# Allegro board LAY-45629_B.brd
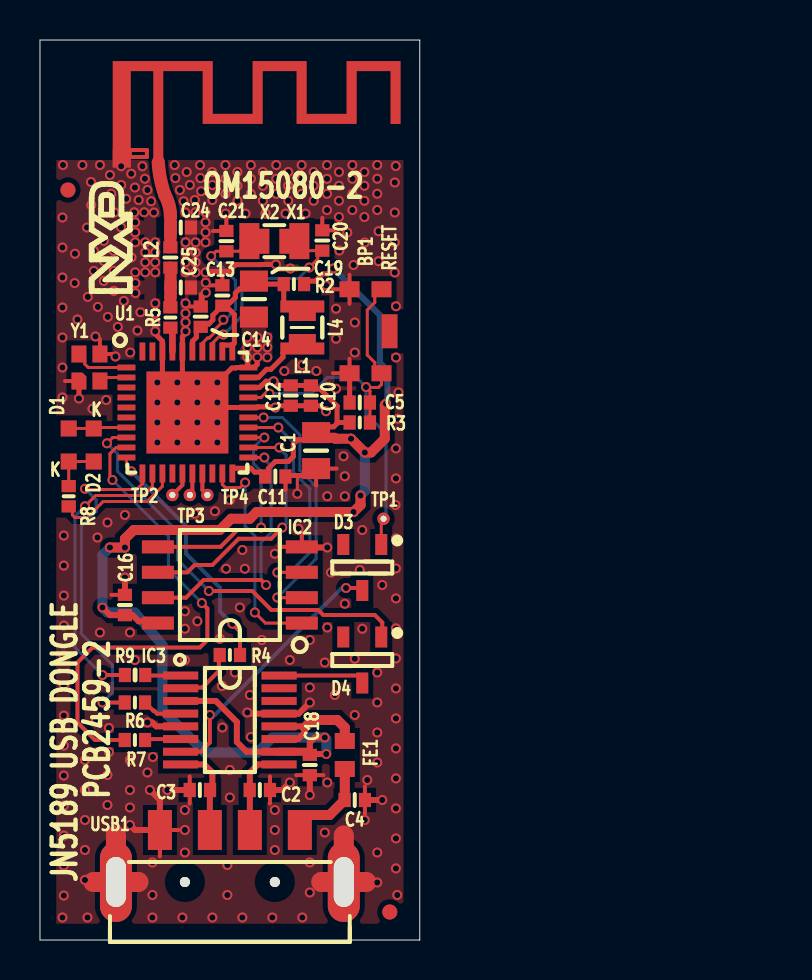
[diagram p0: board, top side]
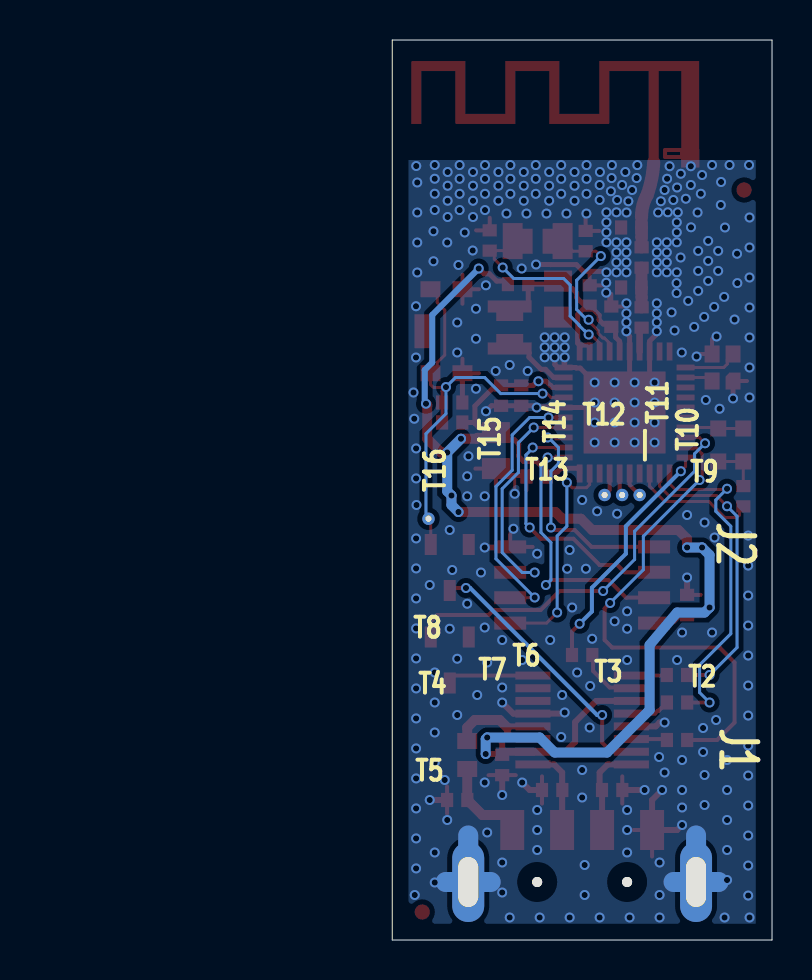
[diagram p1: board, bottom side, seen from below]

Outline 19 x 45 mm; copper layers: TOP, BOTTOM. Coordinates in mm from the lower left corner of the outline.
Outline path: 0,45 0,0 19,0 19,45 0,45

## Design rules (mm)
constraint set DEFAULT: min track width 0.15
net group ALIM: nets VCC_USB VDD
net group DEFAUT: nets N16811154 N16827974 N16827980 N16827994 N16828020 N16828026 N16828032 N16828083 N16828101 N16828111 N16845253 N16845589 N16845639 N16845653 N16845667 PIO_4/PWM4-PU PIO_5/ISP_ENTRY PIO_6/PWM6-PD PIO_7/PWM7-PD PIO_8/USART0_TXD PIO_9/USART0_RXD PIO_10/I2C0_SCL PIO_12/SWCLK PIO_13/SWDIO PIO_14/ADC0 PIO_16/SPIFI_CSN PIO_17/SPIFI_IO3 PIO_18/SPIFI_CLK PIO_19/SPIFI_IO0 PIO_20/SPIFI_IO2 PIO_21_SPIFI_IO1 RSTN
net group Z50: nets N16778908 N16845241 N16845609

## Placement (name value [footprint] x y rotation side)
1  BUBBLE-01  [BUBBLE_DIAM8]  25.05 38.5 0 top
9A_X1  BUBBLE-9A  [BUBBLE_DIAM8]  27 15.62 0 top
10A_X1  BUBBLE-10A  [BUBBLE_DIAM8]  36.62 32.88 0 top
ANT1  NC  [PCB_ANT_APPS]  5.92 38.88 0 top
BP1  KMR221GLFS  [BP_KMR]  16.29 30.44 270 top
C1  10uF  [C0805]  13.81 24.47 90 top
C2  47pF  [C0402]  11 7.5 0 top
C3  47pF  [C0402]  8 7.5 180 top
C4  10nF  [C0402]  15.75 7 0 top
C5  10nF  [C0402]  16 26.88 180 top
C10  100nF  [C0402]  13.55 27.22 90 top
C11  100nF  [C0402]  11.78 23.18 0 top
C12  47pF  [C0402]  12.54 27.22 90 top
C13  100nF  [C0402]  9.12 32.23 90 top
C14  47pF  [C0402]  8.04 31.17 90 top
C16  100nF  [C0402]  4.25 16.75 270 top
C18  100nF  [C0402]  13.5 8.75 90 top
C19  10uF  [C0805]  10.71 32.05 270 top
C20  NC  [C0402]  14.12 34.98 270 top
C21  NC  [C0402]  9.32 34.95 90 top
C24  0.8pF  [C0402]  7.04 35.62 180 top
C25  2.0pF  [C0402]  7.04 32.62 180 top
D1  ORANGE  [LED_0603_A_K]  1.44 24.75 90 top
D2  YELLOW-GREEN  [LED_0603_A_K]  2.69 24.75 270 top
D3  BAT754  [SOT23]  16.12 18.62 180 top
D4  BAT754  [SOT23]  16.12 14 180 top
FE1  470R  [BLM18]  15.25 9.25 90 top
FID1  NC  [FID1]  1.4 37.5 0 top
FID2  NC  [FID1]  17.5 1.4 0 top
IC2  MX25R8035F  [SOP8_127_200]  9.5 17.75 90 top
IC3  FT230XS  [JEDEC_MO137_AB_SSOP16]  9.5 11 270 top
L1  4,7uH_NC  [IND_CB_2518_2520]  13.12 30.62 270 top
L2  2.9nH  [SELF_0402]  6.53 34.12 270 top
L4  4.7uH  [0805C_IPCC]  13.12 30.62 270 top
NOREF  -  []  3.54 35.1 90 top
NOREF#2  -  []  0 -0.38 0 top
NOREF#3  -  []  19.38 0 90 top
NOREF#4  -  []  6 38.12 0 top
R2  NC  [R0402]  12.71 32.8 0 top
R3  2K20  [R0402]  16 25.88 180 top
R4  NC  [R0402]  9.5 14.25 180 top
R5  0R  [R0402]  6.53 31.12 270 top
R6  0R  [R0402]  4.75 11.88 0 top
R7  NC  [R0402]  4.75 10 0 top
R8  680R  [R0402]  1.44 22.19 270 top
R9  0R  [R0402]  4.76 13.25 0 top
TP1  NC  [VIA062P030]  17.19 21.06 0 top
TP2  NC  [VIA062P030]  6.62 22.25 0 top
TP3  NC  [VIA062P030]  7.5 22.25 0 top
TP4  NC  [VIA062P030]  8.38 22.25 0 top
U1  JN5189_40  [SOT618-1_HVQFN40_050_JN518X]  7.38 26.38 0 top
USB1  USB-A  [CONN_USB_LUMBERG241007_A]  9.5 -0.1 0 top
X1  32.768Khz_NC  [NX3215SA]  11.72 34.95 180 top
X2  32.768Khz  [NX2012SA]  11.72 34.94 180 top
Y1  32.000Mhz  [NX2016SA]  2.48 28.62 270 top

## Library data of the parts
1 9A_X1 10A_X1 = BUBBLE: alternate symbols: (BUBBLE_DIAM4)
ANT1 = ANTENNA_JN518x: alternate symbols: (pcb_ant_apps_flip)
BP1 = BP_KMR: User Part Number: PARTNUM; Tolerance: TOLERANCE
C1 C19 = CAPA: alternate symbols: (0805C); tolerance: 10%
C2 C3 = CAPA: User Part Number: BCNNUMBER; Tolerance: 1%; alternate symbols: (0402C); tolerance: 1%
C4 C5 C10-C14 C16 C18 = CAPA: User Part Number: BCNNUMBER; Tolerance: 5%; alternate symbols: (0402C); tolerance: 5%
C20 C21 = CAPA: User Part Number: BCNNUMBER; Tolerance: -; alternate symbols: (0402C); tolerance: -
C24 C25 = CAPA: User Part Number: BCNNUMBER; Tolerance: +/-0.1pF; alternate symbols: (0402C); tolerance: +/-0.1pF
D1 D2 = LED
D3 D4 = BAT754: User Part Number: PARTNUM; Tolerance: TOLERANCE
FE1 = FERRITE_2: Tolerance: TOLERANCE; User Part Number: PARTNUM
FID1 FID2 = MIRE
IC2 = MX25R8035F_RST: Tolerance: TOLERANCE; User Part Number: PARTNUM
IC3 = FT230XS: User Part Number: PARTNUM; Tolerance: TOLERANCE
L1 = SELF: Tolerance: TOLERANCE; User Part Number: PARTNUM
L2 = SELF: Tolerance: TOLERANCE; User Part Number: BCNNUMBER
L4 = SELF
R2 R4 R7 = RES: User Part Number: BCNNUMBER; Tolerance: -; tolerance: -
R3 R8 = RES: User Part Number: BCNNUMBER; Tolerance: 1%; alternate symbols: (0402R); tolerance: 1%
R5 R6 R9 = RES: User Part Number: BCNNUMBER; Tolerance: -; alternate symbols: (0402R); tolerance: -
TP1-TP4 = PLOT
U1 = JN518x_QFN40: Tolerance: TOL; User Part Number: PN
USB1 = USB-A
X1 X2 = XTAL
Y1 = XTAL_NX2016_4P

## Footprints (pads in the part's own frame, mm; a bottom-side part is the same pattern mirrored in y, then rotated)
0805C_IPCC
  rect 0.95x1.35 smd: 1(-0.8,0) 2(0.8,0)
BLM18
  rect 0.8x1 smd: 1(-0.7,0) 2(0.7,0)
BP_KMR
  rect 0.8x1 smd: 1(2.1,0.8) 2(2.1,-0.8) 3(-2.1,0.8) 4(-2.1,-0.8)
  rect 1.7x0.8 smd: 5(0,1.2)
BUBBLE_DIAM8
  round 0 smd: 1(0,0)
C0402
  rect 0.61x0.711 smd: 1(-0.508,0) 2(0.508,0)
C0805
  rect 1.05x1.4 smd: 1(-0.9,0) 2(0.9,0)
CONN_USB_LUMBERG241007_A
  round 0.5 hole 1.15 unplated: (-2.25,3) (2.25,3)
  rect 1.2x2 smd: 1(3.5,5.6) 2(1,5.6) 3(-1,5.6) 4(-3.5,5.6)
  oval 1.6x4 hole 1x2.5: 5(-5.7,3) 6(5.7,3)
FID1
  round 0.76 smd: 1(0,0)
IND_CB_2518_2520
  rect 0.6x2.2 smd: 1(-1.05,0) 2(1.05,0)
JEDEC_MO137_AB_SSOP16
  rect 0.4x1.76 smd: 1(-2.223,-2.462) 2(-1.587,-2.462) 3(-0.953,-2.462) 4(-0.318,-2.462) 5(0.318,-2.462) 6(0.953,-2.462) 7(1.587,-2.462) 8(2.223,-2.462) 9(2.223,2.462) 10(1.587,2.462) 11(0.953,2.462) 12(0.318,2.462) 13(-0.318,2.462) 14(-0.953,2.462) 15(-1.587,2.462) 16(-2.223,2.462)
LED_0603_A_K
  rect 0.8x0.8 smd: A(0.825,0) K(-0.825,0)
NX2012SA
  rect 1x1.25 smd: 1(-0.75,0) 2(0.75,0)
NX2016SA
  rect 0.85x0.75 smd: 1(-0.675,-0.525) 3(0.675,0.525) 4(-0.675,0.525)
  custom 0.188x0.188 smd: 2(0.675,-0.525)
NX3215SA
  rect 1x1.8 smd: 1(-1.25,0) 2(1.25,0)
PCB_ANT_APPS
  rect 0.9x0.9 smd: 1(-1.829,0.2)
  rect 0.5x0.5 smd: 3(0,0)
R0402
  rect 0.61x0.711 smd: 1(-0.508,0) 2(0.508,0)
SELF_0402
  rect 0.61x0.711 smd: 1(-0.508,0) 2(0.508,0)
SOP8_127_200
  rect 0.65x1.6 smd: 1(-1.905,-3.6) 2(-0.635,-3.6) 3(0.635,-3.6) 4(1.905,-3.6) 5(1.905,3.6) 6(0.635,3.6) 7(-0.635,3.6) 8(-1.905,3.6)
SOT23
  rect 0.6x1.05 smd: 1(-0.95,-1.15) 2(0.95,-1.15) 3(0,1.15)
SOT618-1_HVQFN40_050_JN518X
  rect 0.9x0.29 smd: 1(-3.05,2.25) 2(-3.05,1.75) 3(-3.05,1.25) 4(-3.05,0.75) 5(-3.05,0.25) 6(-3.05,-0.25) 7(-3.05,-0.75) 8(-3.05,-1.25) 9(-3.05,-1.75) 10(-3.05,-2.25) 21(3.05,-2.25) 22(3.05,-1.75) 23(3.05,-1.25) 24(3.05,-0.75) 25(3.05,-0.25) 26(3.05,0.25) 27(3.05,0.75) 28(3.05,1.25) 29(3.05,1.75) 30(3.05,2.25)
  rect 0.29x0.9 smd: 11(-2.25,-3.05) 12(-1.75,-3.05) 13(-1.25,-3.05) 14(-0.75,-3.05) 15(-0.25,-3.05) 16(0.25,-3.05) 17(0.75,-3.05) 18(1.25,-3.05) 19(1.75,-3.05) 20(2.25,-3.05) 31(2.25,3.05) 32(1.75,3.05) 33(1.25,3.05) 34(0.75,3.05) 35(0.25,3.05) 36(-0.25,3.05) 37(-0.75,3.05) 38(-1.25,3.05) 39(-1.75,3.05) 40(-2.25,3.05)
  rect 4.1x4.1 smd: 41(0,0)
VIA062P030
  round 0.62 hole 0.31: 1(0,0)

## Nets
GND: ANT1.1 BP1.2 BP1.4 C1.1 C2.2 C3.2 C4.2 C5.2 C10.1 C11.2 C12.1 C13.2 C14.2 C16.1 C18.1 C19.2 C20.1 C21.2 C24.1 C25.1 IC2.4 IC3.5 IC3.13 U1.26 U1.30 U1.36 U1.38 U1.41 USB1.4 USB1.5 USB1.6 Y1.2 Y1.4
VCC_USB: FE1.2 IC3.11 IC3.12
VDD: C1.2 C10.2 C11.1 C12.2 C16.2 C18.2 IC2.8 IC3.3(VCCIO) IC3.10 R2.2 R3.2 U1.20 U1.28
PIO_4/PWM4-PU: D1.A D2.K U1.7
PIO_5/ISP_ENTRY: D4.1 U1.8
PIO_6/PWM6-PD: R7.1 U1.9
PIO_7/PWM7-PD: R4.1 U1.10
PIO_8/USART0_TXD: R6.1 U1.11
PIO_9/USART0_RXD: R9.1 U1.12
PIO_10/I2C0_SCL: R8.2 U1.13
PIO_12/SWCLK: TP2.1 U1.15
PIO_13/SWDIO: TP3.1 U1.16
PIO_14/ADC0: TP4.1 U1.17
PIO_16/SPIFI_CSN: IC2.1 U1.19
PIO_17/SPIFI_IO3: IC2.7 U1.21
PIO_18/SPIFI_CLK: IC2.6 U1.22
PIO_19/SPIFI_IO0: IC2.5 U1.23
PIO_20/SPIFI_IO2: IC2.3(W\P\/SIO2) U1.24
PIO_21_SPIFI_IO1: IC2.2 U1.25
RSTN: BP1.1 BP1.3 C5.1 D3.1 R3.1 TP1.1 U1.27
N16778908: ANT1.3(IN) C24.2 L2.1
N16811154: D1.K D2.A R8.1
N16827974: IC3.1 R9.2
N16827980: IC3.2 R4.2
N16827994: IC3.4 R6.2
N16828020: IC3.6 R7.2
N16828026: D3.3(CATHODE) IC3.7
N16828032: D4.3(CATHODE) IC3.16
N16828083: C3.1 IC3.8 USB1.3
N16828101: C2.1 IC3.9 USB1.2
N16828111: C4.1 FE1.1 USB1.1(VCC)
N16845241: C25.2 L2.2 R5.1
N16845253: U1.2 Y1.3
N16845589: U1.1(XTAL_P) Y1.1
N16845609: R5.2 U1.37
N16845639: C13.1 C14.1 C19.1 L1.1 L4.1 R2.1 U1.31 U1.32 U1.35
N16845653: C20.2 U1.33 X1.1 X2.1
N16845667: L1.2 L4.2 U1.29
N16862787: C21.1 U1.34 X1.2 X2.2

Pads without a net: 1 1; 9A_X1 1; 10A_X1 1; BP1 5; D3 2; D4 2; FID1 1; FID2 1; IC3 14 15; U1 3 4 5 6 14 18 39 40

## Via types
v1: diameter 0.5, hole 0.31, TOP to BOTTOM, 383 vias

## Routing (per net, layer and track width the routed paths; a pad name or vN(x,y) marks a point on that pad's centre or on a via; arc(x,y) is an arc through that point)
GND: length 82.3
  TOP w0.15: v1(12.88,22.31) 12.88,23.23
  TOP w0.2: 13.81,22.72 C1.1 14.84,23.57 ; 11.51,8.18 C2.2 11.51,6.82 ; 3,30.05 Y1.4 3.7,29.3 ; 7.49,8.18 C3.2 7.49,6.82 ; 15.49,31.81 BP1.4 ; BP1.4 15.49,33.26 ; BP1.4 14.66,32.54 ; 3.57,17.26 C16.1 ; 12.82,8.24 C18.1 14.18,8.24 ; 12.28,22.49 C11.2 ; U1.30 10.43,29.1 ; 14.81,35.48 C20.1 14.12,36.11 ; 16.26,7.68 C4.2 16.26,6.32 ; BP1.2 15.49,29.06 ; BP1.2 15.49,27.61 ; BP1.2 14.66,28.34 ; IC2.4 14.23,19.66 ; IC2.4 13.1,20.31 ; IC2.4 11.97,19.66 ; 1.25,27.95 Y1.2 ; 8.44,32.73 9.12,32.73 9.12,33.36 ; 7.36,31.67 C14.2 8.04,32.3 ; 6,4.17 USB1.4 6.93,5.5 ; 8.64,35.45 C21.2 9.32,36.08
  TOP w0.25: 6.12,28.12 U1.38 6.12,29.95 5.76,30.3 v1(5.76,30.43) ; v1(14.31,26.44) 14.04,26.71 C10.1 C12.1 11.86,26.71 v1(11.78,26.62) ; v1(11.78,26.62) 11.81,26.59 ; v1(11.78,26.62) 11.74,26.66 10.89,26.66 10.87,26.62 U1.26 9.12,26.62 ; 10.38,28.62 v1(10.38,29.14) ; 10.38,28.62 U1.30 10.71,28.62 10.87,28.77 10.87,29.12 v1(10.88,29.14) ; 10.38,28.62 9.83,28.62 9.8,28.6 9.6,28.6 9.12,28.12 ; v1(8.29,33.38) 8.33,33.43 9.45,33.43 9.79,33.77 11.09,33.77 11.09,33.77 v1(11.8,33.77) ; BP1.2 15.49,28.33 C5.2 ; C11.2 12.33,23.23 13.32,23.23 13.54,23.45 13.87,23.45 ; v1(7.29,30.43) 7.29,30.34 7.12,30.18 U1.36 7.12,28.12 ; C14.2 8.12,31.75 8.12,32.19 v1(8.29,32.37) ; Y1.2 v1(1.95,27.07)
  TOP w0.3: v1(4.5,5.75) 4.75,5.5 USB1.4 6,7 v1(5.5,7.5) ; v1(5.38,10.88) 5.62,10.88 5.82,10.68 IC3.5 ; C2.2 12.12,7.5 v1(12.5,7.88) ; C16.1 v1(4.25,18.12) ; C3.2 v1(6.38,7.5) ; v1(13.5,11.88) 12.94,11.32 IC3.13 10.43,11.32 v1(10.38,11.38) ; IC2.4 13.13,19.62 v1(14.38,19.62) ; C18.1 v1(13.5,7.25) ; C4.2 v1(17.12,7)
  TOP w1: USB1.5 4.93,2.9 ; USB1.5 2.67,2.9 ; USB1.5 3.8,5.23 ; USB1.6 15.2,5.23 ; USB1.6 16.33,2.9 ; USB1.6 14.07,2.9
  BOTTOM w1: 14.07,2.9 USB1.6 ; USB1.6 15.2,5.23 ; USB1.6 16.33,2.9 ; USB1.5 4.93,2.9 ; USB1.5 3.8,5.23 ; USB1.5 2.67,2.9
  vias: v1(1.15,38.75) v1(1.12,36.12) v1(1.12,34.62) v1(1.12,33.12) v1(1.12,31.62) v1(1.12,30.12) v1(1.12,28.62) v1(1.12,27.12) v1(1.12,1.12) v1(1.19,20.22) v1(1.19,18.72) v1(1.19,17.22) v1(1.19,15.72) v1(1.19,14.22) v1(1.19,12.72) v1(1.19,11.22) v1(1.19,9.72) v1(1.19,8.22) v1(1.19,6.72) v1(1.19,5.22) v1(1.19,3.72) v1(1.19,2.22) v1(1.74,32.84) v1(1.75,34.31) v1(1.88,31.02) v1(2.12,38.75) v1(2.25,9) v1(2.25,7.5) v1(2.25,6) v1(2.25,4.5) v1(2.25,3) v1(2.35,35.62) v1(2.4,32.16) v1(2.38,1.12) v1(2.55,37.9) v1(2.56,36.75) v1(2.62,26.56) v1(2.69,34.45) v1(2.69,33.45) v1(2.77,30.18) v1(2.8,11) v1(2.9,31.66) v1(2.88,20.12) v1(3,38.75) v1(3,15.38) v1(3.19,34.95) v1(3.19,33.95) v1(3.19,32.95) v1(3.31,27) v1(3.4,31.16) v1(3.38,20.88) v1(3.38,8.25) v1(3.38,6.75) v1(3.5,38.25) v1(3.45,10.6) v1(3.45,9.4) v1(3.56,37.31) v1(3.73,36.38) v1(3.69,34.45) v1(3.69,33.45) v1(3.69,32.45) v1(3.77,29.18) v1(3.9,30.66) v1(4.06,38.69) v1(4.06,37.75) v1(4.05,35.63) v1(4.2,31.95) v1(4.25,21.25) v1(4.31,37.06) v1(4.51,29.38) v1(4.5,15.38) v1(4.5,9) v1(4.5,7.5) v1(4.5,6.62) v1(4.56,38.31) v1(4.58,34.12) v1(4.71,36.38) v1(4.75,37.62) v1(4.76,35.88) v1(4.76,35.38) v1(4.76,34.88) v1(4.76,33.38) v1(4.78,32.84) v1(4.78,32.34) v1(4.75,14) v1(4.94,37) v1(4.88,30.48) v1(5.03,31.39) v1(5.12,38.69) v1(5.25,38.06) v1(5.21,36.38) v1(5.26,34.88) v1(5.26,34.38) v1(5.26,33.88) v1(5.26,33.38) v1(5.38,37.5) v1(5.38,8.38) v1(5.56,36.94) v1(5.62,3.88) v1(5.62,2.25) v1(5.62,1.12) v1(5.7,36.38) v1(5.65,9.15) v1(5.76,34.88) v1(5.76,34.38) v1(5.76,33.88) v1(5.76,33.38) v1(5.76,31.84) v1(5.76,31.34) v1(5.76,30.89) v1(5.88,27.88) v1(5.88,26.88) v1(5.88,25.88) v1(5.88,24.88) v1(6.74,38.75) v1(6.78,38.1) v1(6.88,27.88) v1(6.88,26.88) v1(6.88,25.88) v1(6.88,24.88) v1(7,37.5) v1(7.12,1.12) v1(7.19,36.94) v1(7.25,16.44) v1(7.25,15.56) v1(7.25,14) v1(7.25,6.5) v1(7.25,5.5) v1(7.25,4.38) v1(7.34,38.4) v1(7.28,36.38) v1(7.29,34.88) v1(7.29,34.38) v1(7.29,33.88) v1(7.29,33.38) v1(7.29,31.84) v1(7.29,31.34) v1(7.29,30.89) v1(7.5,37.75) v1(7.75,37) v1(7.79,36.38) v1(7.79,34.88) v1(7.79,34.38) v1(7.79,33.88) v1(7.79,33.38) v1(7.75,21.31) v1(7.88,27.88) v1(7.88,26.88) v1(7.88,25.88) v1(7.88,24.88) v1(7.88,15.94) v1(8.01,38.75) v1(8.03,38.1) v1(8.06,37.44) v1(8.29,36.38) v1(8.29,35.88) v1(8.29,35.38) v1(8.29,34.88) v1(8.29,32.87) v1(8.61,38.4) v1(8.62,37.75) v1(8.62,37) v1(8.62,1.12) v1(8.75,21.44) v1(8.88,27.88) v1(8.88,26.88) v1(8.88,25.88) v1(8.88,24.88) v1(9,15.06) v1(9.1,12.7) v1(9.12,10.62) v1(9.28,38.75) v1(9.28,38.06) v1(9.28,37.31) v1(9.29,36.32) v1(9.31,18.56) v1(9.38,3.75) v1(9.38,2.25) v1(9.5,22) v1(9.5,8.5) v1(9.5,7.12) v1(9.75,13.38) v1(9.88,38.4) v1(9.88,37.71) v1(9.88,36.96) v1(10,16.62) v1(10.12,19.5) v1(10.12,1.12) v1(10.25,18.56) v1(10.29,36.32) v1(10.38,30.14) v1(10.38,29.64) v1(10.5,12.25) v1(10.55,38.75) v1(10.55,38.06) v1(10.55,37.31) v1(10.55,10.15) v1(10.88,30.14) v1(10.88,29.64) v1(11.1,15) v1(11.15,38.4) v1(11.15,37.71) v1(11.15,36.96) v1(11.29,36.32) v1(11.38,30.14) v1(11.38,29.64) v1(11.38,29.14) v1(11.62,1.12) v1(11.82,38.75) v1(11.82,38.06) v1(11.82,37.31) v1(11.75,19.31) v1(11.75,6.5) v1(11.75,5.5) v1(11.75,4.5) v1(12.22,28.45) v1(12.29,36.32) v1(12.42,38.4) v1(12.42,37.71) v1(12.42,36.96) v1(12.53,33.58) v1(12.5,14) v1(12.94,20.56) v1(13.09,38.75) v1(13.09,38.06) v1(13.09,37.31) v1(13.12,28.75) v1(13.12,1.12) v1(13.29,36.32) v1(13.5,15) v1(13.5,12.62) v1(13.5,3.88) v1(13.5,2.38) v1(13.69,38.4) v1(13.69,37.71) v1(13.69,36.96) v1(13.82,28.45) v1(14.25,13.88) v1(14.25,5.38) v1(14.31,32.73) v1(14.36,38.75) v1(14.36,38.06) v1(14.36,37.31) v1(14.36,36.5) v1(14.38,22.19) v1(14.38,15.62) v1(14.38,7.88) v1(14.56,18.38) v1(14.81,31.56) v1(14.81,30.06) v1(14.81,27.56) v1(14.75,12.25) v1(14.96,38.4) v1(14.96,37.71) v1(14.96,36.96) v1(14.96,36.15) v1(14.97,34.48) v1(15.19,24.19) v1(15.25,23.19) v1(15.25,22.19) v1(15.25,16.81) v1(15.38,35.38) v1(15.63,38.75) v1(15.63,38.06) v1(15.63,37.31) v1(15.63,36.5) v1(15.69,33.75) v1(15.75,30.88) v1(15.75,29.38) v1(15.75,14.06) v1(15.75,11.25) v1(16,18.5) v1(16.12,20.5) v1(16.12,15.56) v1(16.23,38.4) v1(16.23,37.71) v1(16.23,36.96) v1(16.23,36.15) v1(16.25,34.88) v1(16.25,6) v1(16.38,8) v1(16.88,38.75) v1(16.88,38.06) v1(16.88,37.31) v1(16.88,36.5) v1(16.94,35.44) v1(16.94,33.94) v1(16.88,13.38) v1(16.88,11.88) v1(16.88,10.38) v1(16.88,8.88) v1(16.88,4.38) v1(16.88,2.88) v1(17.12,17.75) v1(17.8,38.7) v1(17.75,37.88) v1(17.75,36.38) v1(17.75,34.88) v1(17.75,33.38) v1(17.81,31.69) v1(17.81,29.12) v1(17.81,24.58) v1(17.81,23.08) v1(17.79,21.75) v1(17.81,20.08) v1(17.81,18.58) v1(17.81,17.08) v1(17.81,15.58) v1(17.81,14.08) v1(17.81,12.58) v1(17.81,11.08) v1(17.81,9.58) v1(17.81,8.08) v1(17.81,6.58) v1(17.81,5.08) v1(17.81,3.58) v1(17.94,27.38) v1(17.9,26.06) v1(17.88,2.25)
VCC_USB: length 6
  TOP w0.3: IC3.11 12.92,10.05 13.25,10.38 13.25,10.62 13.19,10.68 IC3.12
  TOP w0.5: FE1.2 15.25,10.62 14.88,11 13.62,11 13.25,10.62
VDD: length 83.5
  TOP w0.25: U1.28 10.97,27.62 11.07,27.73 11.09,27.73 11.3,27.94 v1(11.69,27.94) 11.75,27.94 11.96,27.73 C12.2 C10.2 13.72,27.56 14,27.56 14.87,26.7 14.87,25.83 ; 14.87,25.83 14.91,25.88 R3.2 ; 14.87,25.83 14.7,25.66 14.15,25.66 ; 14.15,25.66 14.11,25.66 C1.2 ; 14.15,25.66 13.87,25.37 C1.2 ; C1.2 13.63,25.37 13.28,25.01 12.88,25.01 12.68,24.8 12.68,24.18 12.43,23.93 11.78,23.93 11.43,23.57 11.43,23.33 C11.1 11.05,23.39 10.74,23.39 10.55,23.59 9.62,23.59 U1.20 ; v1(14.68,33.58) 14.41,33.31 14.14,33.31 13.78,32.95 13.36,32.95 13.21,32.8 ; 15.49,25.13 v1(15.56,25.06)
  TOP w0.3: 13.54,9.3 C18.2 ; 13.54,9.3 v1(14.33,9.3) ; 13.54,9.3 13.5,9.3 13.5,9.88 13.75,10.12 v1(14.25,10.12) ; IC2.8 5.81,15.94 4.94,15.94 4.63,16.24 C16.2 3.51,16.24 v1(3.12,16.62) ; IC3.3 8.8,11.95 9.85,10.9 9.85,9.9 10.34,9.41 IC3.10
  TOP w0.4: IC3.10 13.39,9.41 13.5,9.3
  TOP w0.5: v1(3.5,19.62) v1(4.25,19.62) 4.25,20.06 4.69,20.5 9,20.5 9.56,21.06 10.5,21.06 10.84,21.4 v1(15.69,21.4) 16.04,21.75 v1(16.04,22.23) ; 14.07,25.11 14.72,25.11 14.77,25.06 v1(15.56,25.06) v1(16.25,24.38) 16.56,24.38 17.25,25.06 17.25,26.75 v1(17.31,26.81) ; 14.07,25.11 C1.2 ; 14.07,25.11 14.03,25.11 13.77,25.37
  BOTTOM w0.3: v1(14.68,33.58) 17,31.25 17,28.88 17.38,28.5 17.38,26.88 v1(17.31,26.81)
  BOTTOM w0.5: v1(15.56,25.06) v1(16.25,24.38) 16.25,22.44 v1(16.04,22.23) 16.04,21.75 v1(15.69,21.4) ; v1(4.25,19.62) v1(3.5,19.62) 3.12,19.25 v1(3.12,16.62) 3.38,16.38 4.75,16.38 6.12,14.75 6.12,11.5 8.25,9.38 10.88,9.38 11.62,10.12 v1(14.25,10.12) 14.33,10.05 v1(14.33,9.3)
PIO_4/PWM4-PU: length 2.9
  TOP w0.15: D1.A D2.K 2.74,25.62 U1.7
PIO_5/ISP_ENTRY: length 20.7
  TOP w0.15: v1(3.35,24.84) 3.64,25.12 U1.8
  TOP w0.2: v1(8.45,17.45) 10.62,17.45 11.57,16.5 13.92,16.5 14.17,16.25 16.75,16.25 17.12,15.88 17.12,15.2 D4.1
  BOTTOM w0.15: v1(3.35,24.84) 3.88,24.31 3.88,23.44 6.88,20.44 6.88,19.02 v1(8.45,17.45)
PIO_6/PWM6-PD: length 25
  TOP w0.15: v1(3.62,23) 3.5,23.12 3.5,24.31 3.81,24.62 U1.9
  TOP w0.2: R7.1 2.75,10 1.88,10.88 1.88,13.88 2.62,14.62 8,14.62 8.38,15 8.38,16.57 v1(8.1,16.85)
  BOTTOM w0.15: v1(8.1,16.85) 6.44,18.51 6.44,20.19 v1(3.62,23)
PIO_7/PWM7-PD: length 12.2
  TOP w0.15: v1(4.56,23.44) 4.33,23.68 U1.10
  TOP w0.2: R4.1 10.01,15.43 v1(9.62,15.81)
  BOTTOM w0.2: v1(4.56,23.44) 7.31,20.69 7.31,19.31 9.01,17.61 9.01,16.43 v1(9.62,15.81)
PIO_8/USART0_TXD: length 16.7
  TOP w0.15: U1.11 5.12,22.81 4.84,22.52 2.29,22.52 v1(2.25,22.56)
  TOP w0.2: R6.1 v1(3.12,11.88)
  BOTTOM w0.15: v1(3.12,11.88) 3.62,12.38 3.62,13.75 2.06,15.31 2.06,20.69 2.81,21.44 2.81,22 v1(2.25,22.56)
PIO_9/USART0_RXD: length 14.8
  TOP w0.15: v1(2.25,21.69) 2.79,22.23 5.16,22.23 5.62,22.69 U1.12
  TOP w0.2: R9.1 v1(3.12,13.25)
  BOTTOM w0.15: v1(3.12,13.25) 1.75,14.62 1.75,21.19 v1(2.25,21.69)
PIO_10/I2C0_SCL: length 6.3
  TOP w0.15: R8.2 1.62,21.49 1.62,21.25 1.75,21.12 2.36,21.12 3.16,21.93 5.36,21.93 6.12,22.69 U1.13
PIO_12/SWCLK: length 1.3
  TOP w0.2: TP2.1 7.12,22.75 U1.15
PIO_13/SWDIO: length 1.1
  TOP w0.2: U1.16 7.62,22.38 TP3.1
PIO_14/ADC0: length 1.2
  TOP w0.2: TP4.1 8.12,22.5 U1.17
PIO_16/SPIFI_CSN: length 11.1
  TOP w0.15: U1.19 9.12,22.77 9.29,22.61 10.01,22.61 v1(10.27,22.88) ; v1(10.75,16.38) 11.28,15.85 IC2.1
  BOTTOM w0.15: v1(10.75,16.38) 10.75,20.2 10.27,20.69 v1(10.27,22.88)
PIO_17/SPIFI_IO3: length 13.5
  TOP w0.15: U1.21 v1(11.22,24.12)
  TOP w0.2: v1(11.31,17.75) 11.06,18 8.19,18 7.3,17.11 IC2.7
  BOTTOM w0.15: v1(11.22,24.12) 11.22,24.02 11.56,23.69 11.56,20.38 11.06,19.88 11.06,18 v1(11.31,17.75)
PIO_18/SPIFI_CLK: length 12.9
  TOP w0.15: U1.22 v1(11.97,24.62)
  TOP w0.2: v1(12.12,20.62) 11.56,20.06 9.94,20.06 8.62,18.75 7.74,18.75 7.38,18.39 IC2.6
  BOTTOM w0.15: v1(12.12,20.62) 12.31,20.81 12.31,24.25 11.97,24.59 v1(11.97,24.62)
PIO_19/SPIFI_IO0: length 11.3
  TOP w0.15: U1.23 v1(11.22,25.12)
  TOP w0.2: IC2.5 9.03,19.66 9.88,20.5 10.94,20.5 v1(11.06,20.62)
  BOTTOM w0.15: v1(11.06,20.62) 11.06,23.44 10.69,23.81 10.69,24.62 11.19,25.12 v1(11.22,25.12)
PIO_20/SPIFI_IO2: length 11.7
  TOP w0.15: v1(11.88,18.38) 11.88,18.39 IC2.3 ; v1(11.93,25.62) U1.24
  BOTTOM w0.15: v1(11.88,18.38) 12.5,18.38 13.5,19.38 13.5,22.56 12.69,23.38 12.69,24.86 v1(11.93,25.62)
PIO_21_SPIFI_IO1: length 13.4
  TOP w0.15: U1.25 v1(11.19,26.12) ; IC2.2 11.88,17.11 v1(11.88,17.12)
  BOTTOM w0.15: v1(11.88,17.12) 13.81,19.06 13.81,22.67 13,23.49 13,25.25 12.12,26.12 v1(11.19,26.12)
RSTN: length 22.9
  TOP w0.15: R3.1 C5.1 16.51,27.45 16.33,27.62 ; v1(11.48,27.32) 11.26,27.32 11.06,27.12 U1.27 ; D3.1 17.07,20.95 TP1.1 ; BP1.3 16.75,32.2 16.75,31.88 16.38,31.5 16.38,29.25 16.75,28.88 16.75,28.68 BP1.1 17.09,27.77 16.94,27.62 16.33,27.62 ; 16.33,27.62 v1(16.31,27.65)
  BOTTOM w0.15: v1(11.48,27.32) 13.57,27.32 14.38,28.12 15.83,28.12 v1(16.31,27.65) 16.31,26.31 17.31,25.31 17.31,21.19 TP1.1
N16778908: length 4.8
  TOP w0.6: 6.53,35.14 6.53,35.15 6.53,35.62 6.53,35.62 arc(6.53,35.68) 6.53,35.74 6.53,35.83 6.53,36.16 ; 6.53,35.14 L2.1 ; 6.53,35.14 6.53,35.61 C24.2
  TOP w0.66: ANT1.3 arc(6.03,38.05) 6.25,37.25 arc(6.46,36.72) 6.53,36.16
N16811154: length 2.5
  TOP w0.15: R8.1 D1.K D2.A
N16827974: length 1.8
  TOP w0.2: 5.29,13.22 5.29,13.22 5.26,13.25 ; 5.29,13.22 IC3.1 ; 5.29,13.22 R9.2
N16827980: length 3.1
  TOP w0.2: IC3.2 7.08,12.62 8.12,12.62 8.95,13.45 8.95,14.21 R4.2
N16827994: length 2
  TOP w0.2: R6.2 5.67,11.46 5.71,11.46 5.86,11.32 IC3.4
N16828020: length 1.8
  TOP w0.2: IC3.6 5.31,10.05 R7.2
N16828026: length 13.3
  TOP w0.2: v1(8.5,11.25) 8.5,9.88 8.04,9.41 IC3.7 ; v1(15.31,17.6) 16,17.6 D3.3
  BOTTOM w0.2: v1(8.5,11.25) 8.75,11.25 15.1,17.6 v1(15.31,17.6)
N16828032: length 4.4
  TOP w0.2: IC3.16 15.9,13.22 16.12,13 D4.3
N16828083: length 4.7
  TOP w0.3: USB1.3 8.5,7.49 C3.1 8.62,7.62 8.62,8.38 8.22,8.78 IC3.8
N16828101: length 4.5
  TOP w0.3: USB1.2 10.5,7.49 C2.1 10.5,7.51 10.5,8.38 10.9,8.78 IC3.9
N16828111: length 4.7
  TOP w0.5: USB1.1 13,6 13.25,6.25 14.49,6.25 C4.1 15.25,7.01 FE1.1
N16845241: length 2
  TOP w0.6: 6.53,32.63 6.53,32.62 6.53,32.62 6.53,32.15 6.53,32.14 R5.1 ; 6.53,32.63 C25.2 ; 6.53,32.63 6.53,33.61 L2.2
N16845253: length 1.4
  TOP w0.15: U1.2 3.17,28.12 Y1.3
N16845589: length 2.8
  TOP w0.15: U1.1 2.42,28.62 2.23,28.8 2.23,29.02 Y1.1
N16845609: length 1.2
  TOP w0.33: R5.2 6.62,30.52 U1.37
N16845639: length 12.1
  TOP w0.25: U1.35 7.62,29.93 7.83,30.13 7.83,30.44 C14.1 8.18,30.8 8.44,30.8 8.65,31 8.65,31.24 9.12,31.72 9.28,31.72 ; U1.32 9.12,29.75 9.62,29.75 ; 9.62,29.75 9.72,29.84 9.72,31.27 9.28,31.72 ; 9.62,29.75 U1.31 ; 9.28,31.72 9.37,31.72 9.78,32.12 9.78,32.34 10,32.56 10.32,32.56 C19.1 10.86,32.8 R2.1 12.2,31.86 12.38,31.68 L1.1
N16845653: length 10.4
  TOP w0.15: X1.1 12.97,34.71 13.21,34.47 C20.2 13.89,34.24 13.89,34.05 v1(13.47,33.62) ; v1(9.18,30.27) 9.06,30.27 8.62,29.84 U1.33
  BOTTOM w0.15: v1(9.18,30.27) 9.35,30.45 9.37,30.45 9.65,30.73 9.65,30.75 10.1,31.2 10.1,32.75 10.43,33.08 12.93,33.08 v1(13.47,33.62)
N16845667: length 3.4
  TOP w0.25: U1.29 10.93,28.12 11.34,28.54 11.55,28.54 12.16,29.14 12.16,29.36 12.38,29.57 L1.2
N16862787: length 8.3
  TOP w0.15: v1(9.18,31.01) 9.18,30.95 8.7,30.47 8.7,30.34 8.46,30.1 8.39,30.1 8.12,29.84 U1.34 ; X1.2 9.97,34.44 C21.1 8.81,34.44 v1(8.56,34.2)
  BOTTOM w0.15: v1(8.56,34.2) 9.78,32.98 9.78,31.52 9.26,31.01 v1(9.18,31.01)

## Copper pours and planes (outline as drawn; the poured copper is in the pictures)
GND on TOP (solid shape): 8.64,41.31 10.64,41.31 10.64,43.95 13.34,43.95 13.34,41.31 15.34,41.31 15.34,43.95 18.04,43.95 18.04,40.8 17.54,40.8 17.54,43.45 15.84,43.45 15.84,40.81 12.84,40.81 12.84,43.45 11.14,43.45 11.14,40.81 8.14,40.81 8.14,43.45 6.17,43.45 6.17,38.63 5.67,38.63 5.67,43.45 4.54,43.45 4.54,38.63 3.64,38.63 3.64,43.95 8.64,43.95
GND on TOP: 0.81,0.81 0.81,39 18.19,39 18.19,0.81 ; 26 cut-outs
GND on BOTTOM: 0.81,39 0.81,0.81 18.19,0.81 18.19,39

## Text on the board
Ref Des/Silkscreen Bottom: T9 | T2 | T3 | T12 | T13 | T6 | T7 | T4 | T5 | T8 | T10 | T11 | T14 | T15 | T16 | J1 | J2
Ref Des/Silkscreen Top: RESET | OM15080-2 | JN5189 USB DONGLE | PCB2459-2
DIMENSION: TITRE | TITLE | . | No EVOL | DESSINE/DRAWN | SR-ASCO | REV. | Nbr/Qty | DATE | 13-Nov-19 | EVOLUTION/CHANGE | M.BAUDRY | VERIFIE/CHECKED | NUMERO DOCUMENT/DOCUMENT NUMBER | DESS./DRAWN | APPROUVE/APPROVED | ..-..-.... | VERIF./CHECKED | PAGE | Austin, TX 78735-8598 | 6501 William Cannon Drive West | SEMICONDUCTORS | 7 | OM15080-JN5189 - USB DONGLE | / | LAY-45629 | B
BODY_CENTER: 4 | LAYER1 - TOP LAYER
DEVICE_TYPE_TOP: 5 | LAYER2 - BOTTOM LAYER
User.18: 2 | SILKSCREEN TOP
User.19: 6 | SOLDERMASK BOTTOM
User.22: 1 | PASTEMASK TOP
User.24: 3 | SOLDERMASK TOP
User.25: 7 | OUTLINE
User.37: All rights are reserved. Reproduction in | whole or in part is prohibited without | the written consent of the copyright owner | NXP Semiconductors | 6501 William Cannon Drive West | Austin, TX 78735-8598 | Date | Draw by | Verify | Modifications | SIZE | REV. | IND. | PL. | Date : 13-Nov-2019 | Draw by : SR-ASCO | Checked by: M.BAUDRY | Project : OM15080 | Protection : . | Finition : . | Material : . | File. | Marging : +/-0.1 | Manufact.level : . | Nbr of layers : . | Silkscreen | TOP   :. | BOTTOM:. | 1 | OM15080-JN5189 USB DONGLE | D | C | B | A | 4 | 3 | 2 | A4 | LAY-45629
User.40: Z= 50 Ohm: | - TOP: Wire: 660um, Spare Wire / GND: 150um | - BOTTOM: Ref. layer | <- VIA | Basic MATERIAL,BOARD Thickness:FR4 Low CTEz TG150 | Basic Copper thickness: | SINGLE LAYER | DOUBLE LAYER | MULTILAYER | SILKSCREEN | IMAGEABLE | SOLDERMASK: | MANUFACTURING Level | COATING COPPER | OTHER | SnPb SELECTIVE | SnPb CONSOLIDATED | NI-AU | TOL.GEN +/-0.1mm | . | X | ELECTROLYTIC | CHEMICAL | : . | TOP | LAYERS | 5 | CI:10/10mm;Cu:17,5um | BOT | (.) | STANDARD NFC 93-713 | COLOR | BLUE | WHITE | Scale : 1/1 | DRILL MANUFACTURING
User.41: Scale : 2/1 | ASSEMBLY DRAWING TOP
User.45: K | Y1 | U1 | R9 | R6 | R7 | TP2 | C8 | C7 | IC3 | C3 | TP3 | C24 | C13 | C21 | TP4 | C14 | R4 | X2 | C11 | C2 | X1 | IC2 | L1 | R2 | C19 | D4 | D3 | C4 | USB1 | TP1 | C5 | R3 | D1 | D2 | RESET | R8 | C16 | L2 | R5 | C25 | C12 | C1 | C18 | C10 | L4 | C20 | BP1 | FE1 | OM15080-JN5189 | JN5189 USB DONGLE | LAY-45629 Rev B | FIGURE | FINISHED_SIZE | 0.31 | 1.15 | 2.5x1.0 | DRILL CHART: TOP to BOTTOM | ALL UNITS ARE IN MILLIMETERS | ROTATION | - | 90.000 | PLATED | NON-PLATED | QTY | 387 | 2
